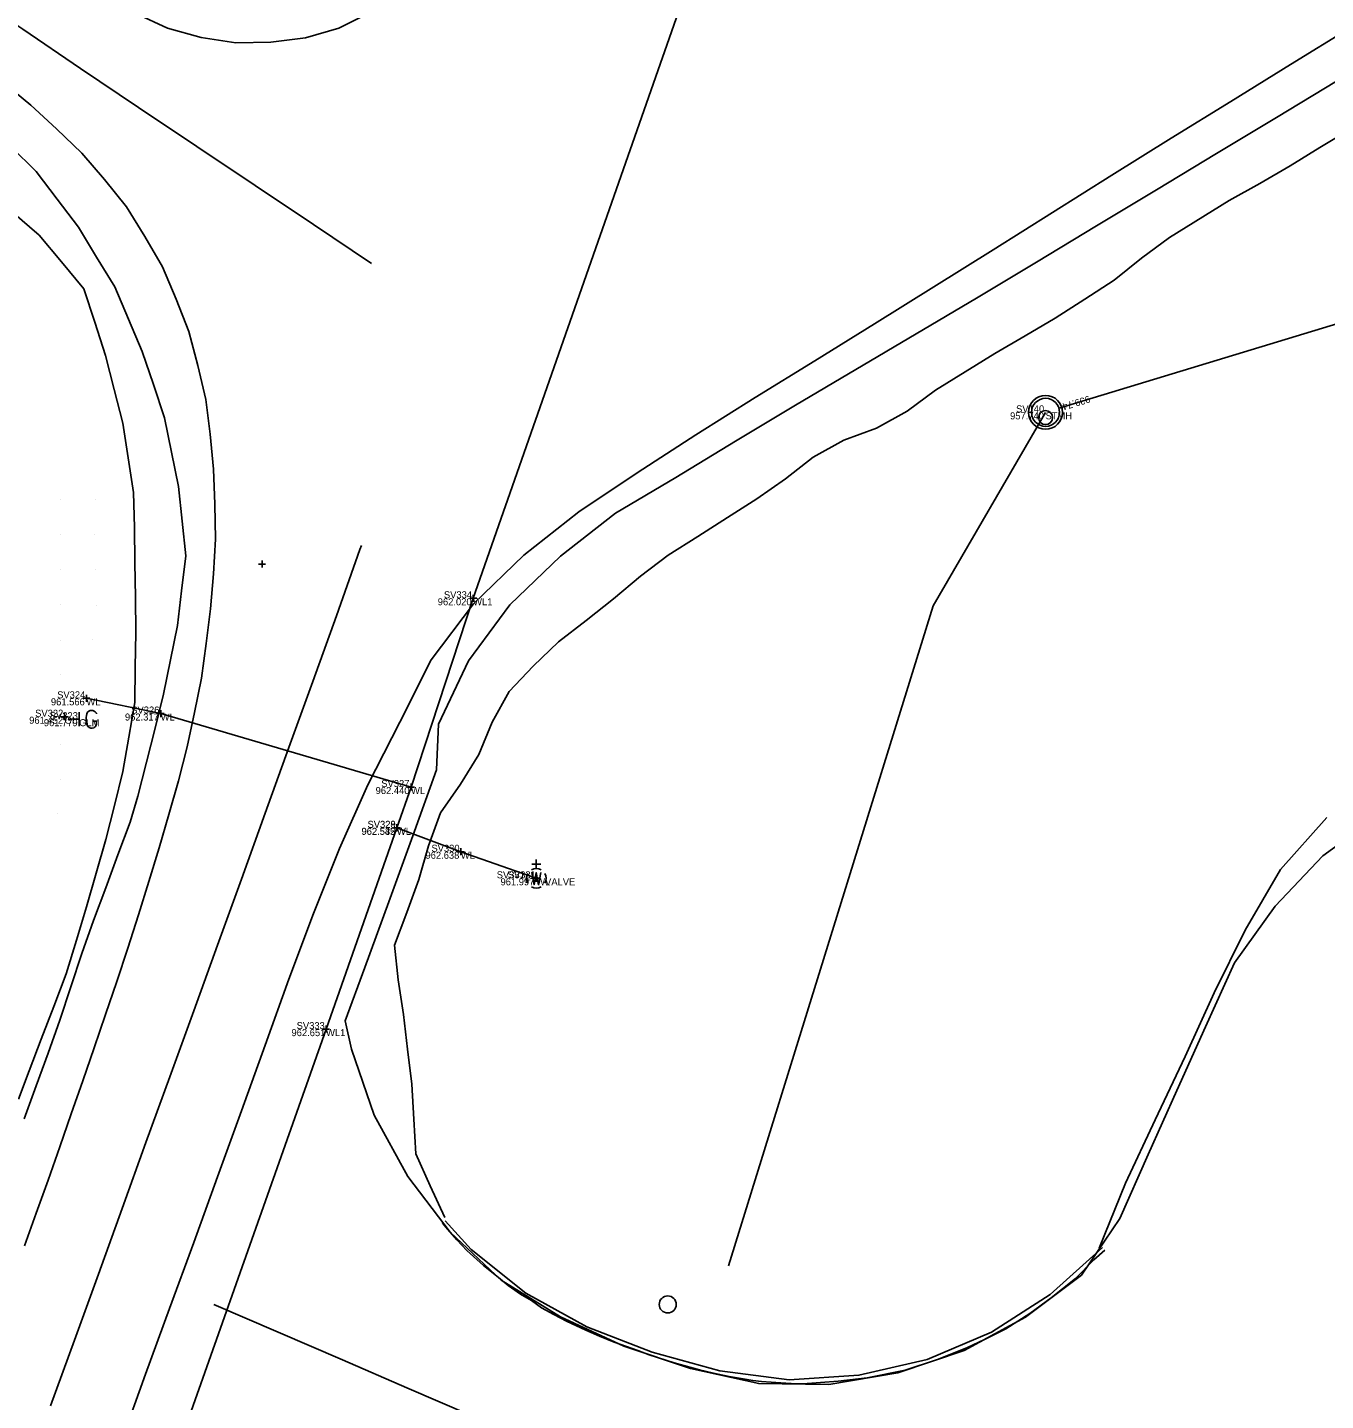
# Model space of a CAD drawing. Extents: x 2262025 to 2264532, y 740981 to 742724.
# Drawn here: x 2263043.2 to 2263228.5, y 741598.2 to 741794.3 of the extents above; entities that cross this region are included whole.
import ezdxf

# ---------------------------------------------------------------- set-up
doc = ezdxf.new("R2010")
doc.units = 0
for name, color, linetype in [('DR_X_Storm_Sewer', 7, 'Continuous'), ('DT_X_Break_Line', 7, 'Continuous'), ('GE_X_Alignment_100_Cardinal_Points', 7, 'Continuous'), ('GE_X_Alignment_100_Curve_Data', 7, 'Continuous'), ('GE_X_Alignment_100_Stations', 7, 'Continuous'), ('GE_X_Alignment_500_Bearings', 7, 'Continuous'), ('Ground Shots', 7, 'Continuous'), ('HY_X_Spring_Cells', 7, 'Continuous'), ('RS_Raster1', 7, 'Continuous'), ('RW_X_CL', 7, 'Continuous'), ('RW_X_CL_1000_Distances', 7, 'Continuous'), ('RW_X_CL_100_Cardinal_Points', 7, 'Continuous'), ('RW_X_CL_100_Curve_Data', 7, 'Continuous'), ('RW_X_CL_100_Stations', 7, 'Continuous'), ('RW_X_CL_500_Curve_Data', 7, 'Continuous'), ('RW_X_CL_500_Stations', 7, 'Continuous'), ('SC_Scratch4', 7, 'Continuous'), ('SV_X_Control_Cells_Found', 7, 'Continuous'), ('SV_X_Text_Comment', 7, 'Continuous'), ('UT_X_Gas_Cells', 7, 'Continuous'), ('UT_X_Water', 7, 'Continuous'), ('UT_X_Water_Cells', 7, 'Continuous')]:
    doc.layers.add(name, color=color, linetype=linetype)

msp = doc.modelspace()

# ---------------------------------------------------------------- linework, layer by layer
at = {"layer": 'DR_X_Storm_Sewer'}
msp.add_line((2263328.09, 741781.86), (2263190.44, 741739.91), dxfattribs=at)
at = {"layer": 'DT_X_Break_Line'}
for points in [[(2263092.31, 741760.6), (2263084, 741766.16), (2263075.69, 741771.72), (2263067.37, 741777.28), (2263059.06, 741782.84), (2263050.77, 741788.43), (2263042.51, 741794.07), (2263034.2, 741799.62), (2263026.31, 741804.81)], [(2263069.82, 741611.95), (2263078.99, 741607.98), (2263088.17, 741604.02), (2263097.35, 741600.05), (2263106.53, 741596.08), (2263115.71, 741592.11), (2263124.89, 741588.14), (2263134.07, 741584.17), (2263143.24, 741580.2), (2263152.42, 741576.23), (2263161.6, 741572.26), (2263170.78, 741568.3), (2263179.9, 741564.19), (2263188.99, 741560.03), (2263189.73, 741559.7)]]:
    msp.add_lwpolyline(points, dxfattribs=at)
at = {"layer": 'GE_X_Alignment_100_Cardinal_Points'}
msp.add_lwpolyline([(2263196.17, 741619.98), (2263199.92, 741629.25), (2263204.17, 741638.3), (2263208.44, 741647.34), (2263212.58, 741656.45), (2263217.02, 741665.4), (2263222.04, 741674.04), (2263228.67, 741681.47)], dxfattribs=at)
at = {"layer": 'GE_X_Alignment_100_Curve_Data'}
for points in [[(2263230.06, 741786.62), (2263221.49, 741781.45), (2263212.93, 741776.28), (2263204.37, 741771.12), (2263195.81, 741765.95), (2263187.24, 741760.79), (2263178.67, 741755.64), (2263170.06, 741750.55), (2263161.46, 741745.46), (2263152.85, 741740.37), (2263144.28, 741735.22), (2263135.74, 741730.02), (2263127.13, 741724.92), (2263119.27, 741718.77), (2263112.05, 741711.85), (2263106.15, 741703.86), (2263101.87, 741694.82), (2263101.56, 741688.28), (2263098.18, 741678.86), (2263094.8, 741669.45), (2263091.34, 741660.07), (2263088.52, 741652.45)], [(2263040.85, 741777.24), (2263044.42, 741773.74), (2263047.44, 741769.76), (2263050.46, 741765.77), (2263053.07, 741761.51), (2263055.68, 741757.24), (2263057.63, 741752.64), (2263059.58, 741748.04), (2263061.17, 741743.3), (2263062.75, 741738.55), (2263063.76, 741733.66), (2263064.77, 741728.76), (2263065.28, 741723.79), (2263065.78, 741718.82), (2263065.2, 741713.85), (2263064.61, 741708.89), (2263063.62, 741703.98), (2263062.63, 741699.08), (2263061.4, 741694.24), (2263060.17, 741689.39), (2263058.95, 741684.54), (2263057.85, 741680.82), (2263056.11, 741676.13), (2263054.37, 741671.44), (2263052.63, 741666.76), (2263050.94, 741662.05), (2263049.38, 741657.3), (2263047.82, 741652.55), (2263046.14, 741647.84), (2263044.43, 741643.14), (2263042.71, 741638.45)]]:
    msp.add_lwpolyline(points, dxfattribs=at)
at = {"layer": 'GE_X_Alignment_100_Stations'}
msp.add_circle((2263134.59, 741611.94), 1.22, dxfattribs=at)
at = {"layer": 'GE_X_Alignment_500_Bearings'}
for points in [[(2263102.45, 741623.54), (2263103.22, 741622.62), (2263104.46, 741621.15), (2263105.93, 741619.64), (2263108.28, 741617.52), (2263110.42, 741615.78), (2263111.8, 741614.63), (2263113.56, 741613.41), (2263115.14, 741612.48), (2263116.56, 741611.46), (2263118.34, 741610.52), (2263120.12, 741609.55), (2263122.88, 741608.27), (2263124.84, 741607.4), (2263126.92, 741606.57), (2263130.3, 741605.35), (2263131.94, 741604.73), (2263135.53, 741603.62), (2263139.12, 741602.6), (2263141.13, 741602.14), (2263143.36, 741601.65), (2263145.37, 741601.31), (2263146.74, 741601.07), (2263147.97, 741600.93), (2263149.37, 741600.82), (2263150.73, 741600.74), (2263152.23, 741600.67), (2263153.88, 741600.59), (2263158.94, 741600.98), (2263163.06, 741601.45), (2263168.47, 741602.54), (2263173.1, 741604.06), (2263177.3, 741605.73), (2263179.79, 741606.94), (2263182.83, 741608.45), (2263186.3, 741610.64), (2263189.33, 741612.86), (2263192.79, 741615.62), (2263195.43, 741618.3), (2263196.96, 741619.68)], [(2263196.63, 741620.05), (2263189.19, 741613.38), (2263180.79, 741607.99), (2263171.6, 741604.09), (2263161.88, 741601.82), (2263151.92, 741601.18), (2263142.02, 741602.46), (2263132.38, 741605.12), (2263123.06, 741608.73), (2263114.32, 741613.54), (2263106.52, 741619.78), (2263102.83, 741623.86)]]:
    msp.add_lwpolyline(points, dxfattribs=at)
at = {"layer": 'Ground Shots'}
for p, q in [((2263047.87, 741726.84), (2263047.87, 741726.84)), ((2263052.9, 741726.88), (2263052.9, 741726.88)), ((2263047.86, 741721.87), (2263047.86, 741721.87)), ((2263052.77, 741721.88), (2263052.77, 741721.88)), ((2263047.88, 741716.88), (2263047.88, 741716.88)), ((2263052.87, 741716.9), (2263052.87, 741716.9)), ((2263047.91, 741711.91), (2263047.91, 741711.91)), ((2263053.02, 741711.75), (2263053.02, 741711.75)), ((2263047.84, 741706.77), (2263047.84, 741706.77)), ((2263052.52, 741706.95), (2263052.52, 741706.95)), ((2263047.87, 741701.89), (2263047.87, 741701.89)), ((2263047.88, 741696.88), (2263047.88, 741696.88)), ((2263047.92, 741691.89), (2263047.92, 741691.89)), ((2263047.87, 741686.93), (2263047.87, 741686.93)), ((2263047.48, 741682.06), (2263047.48, 741682.06))]:
    msp.add_line(p, q, dxfattribs=at)
at = {"layer": 'RW_X_CL_1000_Distances'}
for points in [[(2263058.65, 741796.3), (2263063.19, 741794.19), (2263068, 741792.84), (2263072.93, 741792.08), (2263077.91, 741792.19), (2263082.86, 741792.83), (2263087.64, 741794.19), (2263092.11, 741796.42)], [(2263056.68, 741592.57), (2263060.06, 741601.98), (2263063.49, 741611.37), (2263066.92, 741620.76), (2263070.34, 741630.16), (2263073.73, 741639.57), (2263077.12, 741648.97), (2263080.51, 741658.38), (2263084.01, 741667.75), (2263087.74, 741677.03), (2263091.8, 741686.16), (2263096.36, 741695.07), (2263100.82, 741704.01), (2263106.87, 741711.98), (2263114.07, 741718.91), (2263121.92, 741725.11), (2263130.23, 741730.67), (2263138.62, 741736.1), (2263147.08, 741741.43), (2263155.58, 741746.7), (2263164.09, 741751.95), (2263172.58, 741757.24), (2263181.05, 741762.55), (2263189.52, 741767.87), (2263197.98, 741773.19), (2263206.47, 741778.48), (2263214.98, 741783.74), (2263223.49, 741788.99), (2263232, 741794.24)], [(2263042.77, 741620.29), (2263044.45, 741624.99), (2263046.13, 741629.7), (2263047.8, 741634.42), (2263049.44, 741639.14), (2263051.08, 741643.86), (2263052.72, 741648.59), (2263054.35, 741653.32), (2263055.94, 741658.05), (2263057.52, 741662.8), (2263059.03, 741667.56), (2263060.53, 741672.33), (2263061.97, 741677.12), (2263063.38, 741681.92), (2263064.73, 741686.73), (2263066, 741691.56), (2263067.05, 741696.45), (2263068.02, 741701.36), (2263068.72, 741706.31), (2263069.34, 741711.27), (2263069.74, 741716.25), (2263070.03, 741721.24), (2263069.94, 741726.24), (2263069.76, 741731.23), (2263069.29, 741736.21), (2263068.66, 741741.16), (2263067.53, 741746.03), (2263066.24, 741750.85), (2263064.44, 741755.51), (2263062.47, 741760.1), (2263059.97, 741764.43), (2263057.33, 741768.66), (2263054.21, 741772.56), (2263050.96, 741776.36), (2263047.35, 741779.81), (2263043.67, 741783.19), (2263039.8, 741786.36)]]:
    msp.add_lwpolyline(points, dxfattribs=at)
at = {"layer": 'RW_X_CL_100_Cardinal_Points'}
for p, q in [((2263076.18, 741717.66), (2263077.18, 741717.66)), ((2263076.68, 741718.16), (2263076.68, 741717.16)), ((2263076.68, 741717.66), (2263076.68, 741717.66)), ((2263106.32, 741712.78), (2263107.32, 741712.78)), ((2263106.82, 741713.28), (2263106.82, 741712.28)), ((2263106.82, 741712.78), (2263106.82, 741712.78)), ((2263051.61, 741698.99), (2263051.61, 741697.99)), ((2263051.11, 741698.49), (2263052.11, 741698.49)), ((2263051.61, 741698.49), (2263051.61, 741698.49)), ((2263047.99, 741695.86), (2263048.99, 741695.86)), ((2263048.49, 741696.36), (2263048.49, 741695.36)), ((2263048.49, 741695.86), (2263048.49, 741695.86)), ((2263061.72, 741696.32), (2263062.72, 741696.32)), ((2263062.22, 741696.82), (2263062.22, 741695.82)), ((2263062.22, 741696.32), (2263062.22, 741696.32)), ((2263097.45, 741685.82), (2263098.45, 741685.82)), ((2263097.95, 741686.32), (2263097.95, 741685.32)), ((2263097.95, 741685.82), (2263097.95, 741685.82)), ((2263095.43, 741679.99), (2263096.43, 741679.99)), ((2263095.44, 741680), (2263096.44, 741680)), ((2263095.93, 741680.49), (2263095.93, 741679.49)), ((2263095.93, 741679.99), (2263095.93, 741679.99)), ((2263095.94, 741680.5), (2263095.94, 741679.5)), ((2263095.94, 741680), (2263095.94, 741680)), ((2263104.56, 741676.58), (2263105.56, 741676.58)), ((2263105.06, 741677.08), (2263105.06, 741676.08)), ((2263105.06, 741676.58), (2263105.06, 741676.58)), ((2263115.32, 741672.79), (2263116.32, 741672.79)), ((2263115.82, 741673.29), (2263115.82, 741672.29)), ((2263115.82, 741672.79), (2263115.82, 741672.79)), ((2263085.32, 741651.25), (2263086.32, 741651.25)), ((2263085.82, 741651.75), (2263085.82, 741650.75)), ((2263085.82, 741651.25), (2263085.82, 741651.25))]:
    msp.add_line(p, q, dxfattribs=at)
at = {"layer": 'RW_X_CL_100_Curve_Data'}
for centre, radius in [((2263188.52, 741739.33), 2.42), ((2263188.52, 741739.33), 2.42), ((2263188.52, 741739.33), 2), ((2263188.52, 741739.33), 2), ((2263188.52, 741738.58), 1), ((2263188.52, 741738.58), 1)]:
    msp.add_circle(centre, radius, dxfattribs=at)
at = {"layer": 'RW_X_CL_100_Stations'}
for p, q in [((2263188.52, 741741.33), (2263188.52, 741741.33)), ((2263188.52, 741741.33), (2263188.52, 741741.33)), ((2263188.52, 741739.33), (2263188.52, 741739.33)), ((2263188.52, 741739.33), (2263188.52, 741739.33)), ((2263188.52, 741739.33), (2263188.52, 741739.33)), ((2263188.52, 741739.33), (2263188.52, 741739.33)), ((2263188.52, 741738.58), (2263188.52, 741738.58)), ((2263188.52, 741738.58), (2263188.52, 741738.58)), ((2263188.52, 741737.33), (2263188.52, 741737.33)), ((2263188.52, 741737.33), (2263188.52, 741737.33))]:
    msp.add_line(p, q, dxfattribs=at)
msp.add_circle((2263188.52, 741739.33), 2, dxfattribs=at)
msp.add_circle((2263188.52, 741739.33), 2, dxfattribs=at)
at = {"layer": 'RW_X_CL_500_Curve_Data'}
msp.add_lwpolyline([(2263088.52, 741652.45), (2263089.45, 741648.4), (2263092.69, 741638.97), (2263097.48, 741630.21), (2263103.55, 741622.28), (2263110.79, 741615.41), (2263119.28, 741610.16), (2263128.33, 741605.96), (2263137.82, 741602.8), (2263147.58, 741600.64), (2263157.57, 741600.52), (2263167.43, 741602.16), (2263176.88, 741605.38), (2263185.67, 741610.12), (2263193.64, 741616.14), (2263199.12, 741624.2), (2263203.17, 741633.34), (2263207.25, 741642.47), (2263211.34, 741651.6), (2263215.47, 741660.7), (2263221.32, 741668.81), (2263228.09, 741676), (2263236.18, 741681.87)], dxfattribs=at)
at = {"layer": 'RW_X_CL_500_Stations'}
msp.add_lwpolyline([(2263188.52, 741739.33), (2263172.48, 741711.7), (2263143.24, 741617.44)], dxfattribs=at)
at = {"layer": 'SC_Scratch4'}
msp.add_lwpolyline([(2263046.5, 741597.44), (2263049.91, 741606.85), (2263053.31, 741616.25), (2263056.71, 741625.65), (2263060.11, 741635.06), (2263063.52, 741644.46), (2263066.92, 741653.86), (2263070.32, 741663.26), (2263073.73, 741672.67), (2263077.12, 741682.07), (2263080.52, 741691.48), (2263083.91, 741700.89), (2263087.3, 741710.29), (2263090.64, 741719.72), (2263090.86, 741720.32)], dxfattribs=at)
at = {"layer": 'SV_X_Control_Cells_Found'}
for points in [[(2263102.79, 741624.33), (2263100.7, 741628.88), (2263098.62, 741633.42), (2263098.33, 741638.41), (2263098.05, 741643.4), (2263097.46, 741648.37), (2263096.86, 741653.33), (2263096.09, 741658.27), (2263095.6, 741663.24), (2263097.36, 741667.92), (2263099.06, 741672.62), (2263100.42, 741677.43), (2263102.13, 741682.13), (2263105.01, 741686.21), (2263107.62, 741690.47), (2263109.52, 741695.09), (2263111.94, 741699.46), (2263115.38, 741703.09), (2263118.99, 741706.54), (2263122.94, 741709.6), (2263126.85, 741712.71), (2263130.69, 741715.92), (2263134.66, 741718.95), (2263138.88, 741721.62), (2263143.11, 741724.3), (2263147.33, 741726.97), (2263151.42, 741729.85), (2263155.36, 741732.92), (2263159.73, 741735.34), (2263164.41, 741737.09), (2263168.78, 741739.51), (2263172.8, 741742.48), (2263177.04, 741745.12), (2263181.29, 741747.75), (2263185.61, 741750.27), (2263189.91, 741752.8), (2263194.13, 741755.48), (2263198.31, 741758.22), (2263202.21, 741761.35), (2263206.22, 741764.32), (2263214.72, 741769.59), (2263219.09, 741772.03), (2263223.42, 741774.53), (2263227.68, 741777.14), (2263231.96, 741779.73)], [(2263041.07, 741767.9), (2263044.84, 741764.63), (2263048.05, 741760.8), (2263051.26, 741756.96), (2263052.79, 741752.2), (2263054.32, 741747.44), (2263055.57, 741742.6), (2263056.83, 741737.76), (2263057.59, 741732.82), (2263058.35, 741727.88), (2263058.45, 741722.88), (2263058.54, 741717.88), (2263058.6, 741712.88), (2263058.66, 741707.88), (2263058.59, 741702.88), (2263058.52, 741697.89), (2263057.68, 741692.96), (2263056.83, 741688.03), (2263055.6, 741683.19), (2263054.37, 741678.34), (2263053, 741673.53), (2263051.62, 741668.73), (2263050.18, 741663.94), (2263048.73, 741659.15), (2263046.94, 741654.49), (2263045.14, 741649.82), (2263043.42, 741645.3), (2263041.92, 741641.24)]]:
    msp.add_lwpolyline(points, dxfattribs=at)
at = {"layer": 'UT_X_Gas_Cells'}
for p, q in [((2263050.57, 741695.51), (2263049.62, 741695.51)), ((2263050.57, 741694.51), (2263050.57, 741696.51))]:
    msp.add_line(p, q, dxfattribs=at)
msp.add_lwpolyline([(2263053.05, 741696.26), (2263053.03, 741696.36), (2263052.97, 741696.46), (2263052.87, 741696.56), (2263052.73, 741696.67), (2263052.64, 741696.71), (2263052.56, 741696.73), (2263052.44, 741696.75), (2263052.2, 741696.75), (2263052.1, 741696.73), (2263052.05, 741696.71), (2263051.97, 741696.67), (2263051.81, 741696.56), (2263051.71, 741696.42), (2263051.65, 741696.26), (2263051.61, 741696.04), (2263051.57, 741695.73), (2263051.57, 741695.32), (2263051.59, 741694.98), (2263051.67, 741694.73), (2263051.79, 741694.49), (2263051.89, 741694.41), (2263052.01, 741694.33), (2263052.22, 741694.25), (2263052.44, 741694.25), (2263052.66, 741694.29), (2263052.73, 741694.33), (2263052.81, 741694.37), (2263052.89, 741694.45), (2263052.97, 741694.57), (2263053.05, 741694.75), (2263053.05, 741695.24), (2263052.64, 741695.24)], dxfattribs=at)
at = {"layer": 'UT_X_Water'}
msp.add_line((2263095.93, 741679.99), (2263105.06, 741676.58), dxfattribs=at)
for points in [[(2263058.18, 741572.97), (2263085.82, 741651.25), (2263095.93, 741679.99), (2263097.95, 741685.82), (2263106.82, 741712.78), (2263147.36, 741828.66), (2263178.07, 741920.18), (2263217.98, 742032.49), (2263252.6, 742127.99), (2263295.63, 742247.6), (2263334.95, 742356.22), (2263370.78, 742449.55), (2263413.67, 742573.04), (2263421.38, 742593.43)], [(2263051.61, 741698.49), (2263062.22, 741696.32), (2263097.95, 741685.82), (2263095.94, 741680), (2263095.93, 741679.99)], [(2263105.06, 741676.58), (2263115.82, 741672.79)]]:
    msp.add_lwpolyline(points, dxfattribs=at)
at = {"layer": 'UT_X_Water_Cells'}
for p, q in [((2263115.82, 741674.19), (2263115.82, 741675.46)), ((2263116.46, 741674.82), (2263115.19, 741674.82)), ((2263115.82, 741672.79), (2263115.82, 741672.79))]:
    msp.add_line(p, q, dxfattribs=at)
msp.add_lwpolyline([(2263115.19, 741673.61), (2263115.5, 741671.88), (2263115.82, 741673.61), (2263116.14, 741671.88), (2263116.46, 741673.61)], dxfattribs=at)
for start, end in [(150.0184, 209.9816), (60.0184, 120.0157), (330.0184, 29.9816), (239.9843, 299.9816)]:
    msp.add_arc((2263115.82, 741672.79), 1.4, start, end, dxfattribs=at)

# ---------------------------------------------------------------- texts
at = {"layer": 'HY_X_Spring_Cells'}
for s, p in [('957.740', (2263183.46, 741738.33)), ('957.740', (2263183.46, 741738.33)), ('962.020', (2263101.76, 741711.78)), ('961.566', (2263046.54, 741697.49)), ('961.452', (2263043.44, 741694.86)), ('961.779', (2263045.53, 741694.51)), ('962.317', (2263057.11, 741695.32)), ('962.440', (2263092.89, 741684.82)), ('962.545', (2263090.86, 741678.99)), ('962.532', (2263090.88, 741679)), ('962.638', (2263100.01, 741675.58)), ('961.997', (2263110.72, 741671.79)), ('961.997', (2263110.72, 741671.79)), ('962.651', (2263080.88, 741650.25))]:
    msp.add_text(s, height=1, dxfattribs=at).set_placement(p)
at = {"layer": 'RS_Raster1'}
msp.add_text("939.74'", height=1, rotation=196.9486, dxfattribs=at).set_placement((2263194.72, 741741.74))
at = {"layer": 'RW_X_CL'}
for s, p in [('STMH', (2263188.52, 741738.33)), ('STMH', (2263188.52, 741738.33)), ('WL1', (2263106.82, 741711.78)), ('WL', (2263051.61, 741697.49)), ('GL', (2263048.49, 741694.86)), ('GLM', (2263050.57, 741694.51)), ('WL', (2263062.22, 741695.32)), ('WL', (2263097.95, 741684.82)), ('WL', (2263095.94, 741679)), ('WL', (2263095.93, 741678.99)), ('WL', (2263105.06, 741675.58)), ('WVALVE', (2263115.82, 741671.79)), ('WL', (2263115.82, 741671.79)), ('WL1', (2263085.82, 741650.25))]:
    msp.add_text(s, height=1, dxfattribs=at).set_placement(p)
at = {"layer": 'SV_X_Text_Comment'}
for s, p in [('SV140', (2263184.31, 741739.33)), ('SV140', (2263184.31, 741739.33)), ('SV334', (2263102.64, 741712.78)), ('SV324', (2263047.43, 741698.49)), ('SV326', (2263058.01, 741696.32)), ('SV322', (2263044.29, 741695.86)), ('SV323', (2263046.38, 741695.51)), ('SV327', (2263093.7, 741685.82)), ('SV328', (2263091.73, 741680)), ('SV329', (2263091.74, 741679.99)), ('SV330', (2263100.86, 741676.58)), ('SV331_1', (2263110.18, 741672.79)), ('SV331', (2263111.74, 741672.79)), ('SV333', (2263081.62, 741651.25))]:
    msp.add_text(s, height=1, dxfattribs=at).set_placement(p)

doc.saveas('drawing.dxf')
